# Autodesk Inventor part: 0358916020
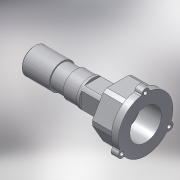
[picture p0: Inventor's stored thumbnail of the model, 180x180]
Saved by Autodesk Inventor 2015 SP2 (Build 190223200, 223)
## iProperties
Created: 2017-01
Part Number: 0358916020
Material: PVC-Piping
Description: SERIES 1 FREE NUT ADAPTOR 20-3/4"-20 (KIT 2 UNITS)
Document SubType Name: Modeling
Designer: Кирилл
Mass: 43.954 g
Surface Area: 139.205 cm^2
Volume: 31.3957 cm^3
Density: 1.4 g/cm^3
Appearance: Smooth - White
Author: KIM
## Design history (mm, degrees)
derived "0358916.ipt"
feature "Solid1::0358916.ipt"
tag "TaggingFeature1"
body "Solid1"
other parameters: "d0" = 85.5, "d1" = 24.117, "d3" = 18, "d4" = 21, "d5" = 42, "d6" = 21.375, "d7" = 5.34375, "d8" = 41.16, "d9" = 5.34375, "d10" = 12, "d11" = 21.375, "d13" = 1, "d14" = 2, "d15" = 8.5, "d17" = 0, "d19" = 360 deg, "d21" = 5, "d22" = 45 deg, "d30" = 0, "d31" = 2, "d34" = 6, "d36" = 0, "d37" = 3, "d39" = 0, "d41" = 360 deg, "d43" = 1, "d44" = 0.6, "G_" = 24.117, "E_" = 42, "H_" = 85.5
